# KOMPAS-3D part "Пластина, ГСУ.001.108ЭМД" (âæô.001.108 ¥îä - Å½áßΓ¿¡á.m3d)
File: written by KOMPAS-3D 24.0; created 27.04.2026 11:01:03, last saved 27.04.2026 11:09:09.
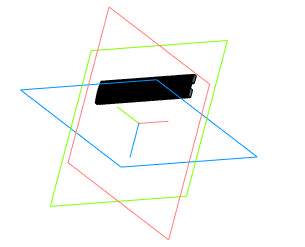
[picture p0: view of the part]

Document properties: Автор: USG_411; Полное имя файла: C:\Users\USG_411\Desktop\ГМ2704_411-15\Двигатель мясорубки\ГСУ.001.108 ЭМД - Пластина.m3d

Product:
- Part/product: Пластина  | designation ГСУ.001.108ЭМД
    Масса: 0.00167

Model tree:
1. Эскиз:1
2. Элемент выдавливания:1
3. Массив по сетке:2  (with: Элемент выдавливания:1, Эскиз:1, Ребро.Элемент выдавливания:1)  (110 pattern instances)
     Угол раствора = 90

Expressions: v18+0.01
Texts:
  ГСУ.001.108
  ГСУ.001.108 ЭМД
